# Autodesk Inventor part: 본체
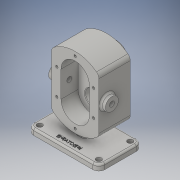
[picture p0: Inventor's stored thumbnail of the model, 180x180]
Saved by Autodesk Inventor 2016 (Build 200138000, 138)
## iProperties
Created: 2019-03
Part Number: 본체
Material: 일반
Document SubType Name: Modeling
Designer: Administrator
Density: 1 g/cm^3
Appearance: 기본값
Mass: 440.333 g
Surface Area: 723.664 cm^2
Volume: 440.333 cm^3
Author: Administrator
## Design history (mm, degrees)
sketch "스케치1"
  geometry: L1 (60, 36.5)-(-60, 36.5); L2 (-60, 36.5)-(-60, -36.5); L3 (-60, -36.5)-(60, -36.5); L4 (60, -36.5)-(60, 36.5); L5 (60, 36.5)-(-60, -36.5); L6 (-60, 36.5)-(60, -36.5); 1 further point
  constraints: 12 end point, 2 midpoint, 2 parallel, 1 horizontal, 1 perpendicular
  dimensions: "d0" = 73 distance of L1.end L2.end; "d1" = 120 distance of L2.end L3.end
extrude "돌출1" new body sketch "스케치1" distance "d2" = 10; taper "d3" = 0 deg
node "작업 평면1"
sketch "스케치2"
  geometry: L1 (0, 0)-(0, 78); L2 (-40, 33.279)-(40, 33.279); L3 (40, 33.279)-(40, 122.721); L4 (-40, 122.721)-(-40, 33.279); L5 (-40, 33.279)-(40, 122.721); L6 (40, 33.279)-(-40, 122.721); L7 (-46.037, 78)-(46.038, 78); A1 r 60 centre (0, 78) between (40, 122.721) and (-40, 122.721); A2 r 60 centre (0, 78) between (-40, 33.279) and (40, 33.279); 2 further points
  constraints: 14 end point, 5 midpoint, 4 point on circle, 2 centre point, 2 horizontal, 1 coincident, 1 parallel, 1 perpendicular, 1 vertical
  dimensions: "d5" = 78 distance of L1.start L1.end; "d6" = 80 distance between parallel lines of L3 L4; "d7" = 60 radius of A1; "d8" = 60 radius of A2
extrude "돌출2" join sketch "스케치2" distance "d9" = 53; taper "d10" = 0 deg
sketch "스케치3"
  geometry: L1 (0, 0)-(0, 78); L2 (-54.769, 78)-(54.769, 78); L3 (0, 100)-(0, 56); L4 (-24, 100)-(-24, 56); L5 (24, 56)-(24, 100); A1 r 24 centre (0, 100) between (24, 100) and (-24, 100); A2 r 24 centre (0, 56) between (-24, 56) and (24, 56); 1 further point
  constraints: 12 end point, 4 point on circle, 4 tangent, 2 centre point, 2 midpoint, 1 coincident, 1 horizontal, 1 parallel, 1 point on line, 1 vertical
  dimensions: "d11" = 78 distance of L1.end L1.start; "d12" = 22 distance of L1.end L3.start; "d13" = 24 radius of A1
extrude "돌출3" cut sketch "스케치3" distance "d14" = 29; taper "d15" = 0 deg
sketch "스케치4"
  geometry: L1 (0, 0)-(0, 78); C1 r 12.5 at (0, 100); C2 r 12.5 at (0, 56)
  constraints: 2 centre point, 2 end point, 2 point on line, 1 equal radius, 1 vertical
  dimensions: "d16" = 78 distance of L1.start L1.end; "d17" = 22 distance of L1.end C1.centre; "d18" = 22 distance of L1.end C2.centre; "d19" = 25 diameter of C1
extrude "돌출4" cut sketch "스케치4" distance "d20" = 15; taper "d21" = 0 deg
sketch "스케치5"
  geometry: C1 r 12.5 at (0, 100) reference; C2 r 19 at (0, 100); 1 further point
  constraints: 1 centre point, 1 concentric
  dimensions: "d22" = 38 diameter of C2
extrude "돌출5" join sketch "스케치5" distance "d23" = 17; taper "d24" = 0 deg
fillet "모깎기1" dims "d29" = 10
fillet "모깎기2" dims "d30" = 3
sketch "스케치7"
  geometry: L1 (-50, 36.5)-(-50, 33.5) reference; L2 (-50, 33.5)-(50, 33.5) reference; L3 (50, 36.5)-(50, 33.5) reference; L4 (50, 36.5)-(-50, 36.5) reference; L5 (-6, 36.5)-(6, 36.5); L6 (6, 36.5)-(6, -6.5); L7 (6, -6.5)-(-6, -6.5); L8 (-6, -6.5)-(-6, 36.5); 1 further point
  constraints: 8 end point, 2 parallel, 1 horizontal, 1 perpendicular, 1 point on line
  dimensions: "d31" = 43 distance of L5.end L6.end; "d32" = 6 distance from line of point (0, 0) L6; "d33" = 6 distance from line of point (0, 0) L8
extrude "돌출6" join sketch "스케치7" stored distance "d34" = 7.3; taper "d35" = 0 deg; dims "d8" = 60
fillet "모깎기3" dims "d36" = 3
fillet "모깎기4" dims "d37" = 10
sketch "스케치8"
  geometry: L1 (81, -53.5)-(119, -53.5) reference; L2 (100, -53.5)-(100, -46.2); L3 (100, -46.2)-(114, -46.2); L4 (114, -46.2)-(114, -52.8); L5 (100, -53.5)-(114.404, -53.5); L6 (114, -52.8)-(114.404, -53.5); 1 further point
  constraints: 10 end point, 1 midpoint, 1 perpendicular, 1 vertical
  dimensions: "d38" = 7.3 distance of L2.start L2.end; "d39" = 14 distance of L2.end L3.end; "d42" = 30 deg angle of L6 L4; "d43" = 6.6 distance of L3.end L4.end
revolve "회전2" sketch "스케치8" stored, may be unused: angle "d44" = 90 deg
sketch "스케치9"
  geometry: C1 r 8.5 at (0, 0); C2 r 19 at (0, 0) reference; 1 further point
  constraints: 1 centre point, 1 concentric
  dimensions: "d45" = 17 diameter of C1
extrude "돌출7" cut sketch "스케치9" stored distance "d46" = 7.3; taper "d47" = 0 deg
chamfer "모따기1" distance "d48" = 1; stored, may be unused: second distance "d49" = 2, angle "d50" = 45 deg
chamfer "모따기2" distance "d51" = 1; stored, may be unused: second distance "d52" = 2, angle "d53" = 45 deg
hole "구멍1" diameter "d56" = 9; stored, may be unused: countersink angle "d60" = 90 deg, drill point angle "d62" = 0 deg; dims "d54" = 10, "d55" = 10, "d57" = 6, "d58" = 4, "d59" = 2, "d61" = 10
hole "구멍2" diameter "d65" = 9; stored, may be unused: countersink angle "d69" = 90 deg, drill point angle "d71" = 0 deg; dims "d63" = 10, "d64" = 10, "d66" = 6, "d67" = 4, "d68" = 2, "d70" = 10
hole "구멍3" diameter "d74" = 9; stored, may be unused: countersink angle "d78" = 90 deg, drill point angle "d80" = 0 deg; dims "d72" = 10, "d73" = 10, "d75" = 6, "d76" = 4, "d77" = 2, "d79" = 10
hole "구멍4" diameter "d83" = 9; stored, may be unused: countersink angle "d87" = 90 deg, drill point angle "d89" = 0 deg; dims "d81" = 10, "d82" = 10, "d84" = 6, "d85" = 4, "d86" = 2, "d88" = 10
fillet "모깎기5" dims "d90" = 3
feature "두껍게 하기1" dims "d91" = 2, "d92" = 2
feature "두껍게 하기2" dims "d93" = 1, "d94" = 1
fillet "모깎기6" dims "d95" = 3
sketch "스케치10"
  geometry: L1 (0, 0)-(0, 78); L2 (0, 100)-(0, 56); L3 (-31, 100)-(-31, 56); L4 (31, 56)-(31, 100); L5 (-31, 100)-(31, 100); L6 (-31, 56)-(31, 56); A1 r 31 centre (0, 100) between (31, 100) and (-31, 100); A2 r 31 centre (0, 56) between (-31, 56) and (31, 56); 9 further points
  constraints: 14 end point, 6 coincident, 6 point on circle, 4 tangent, 2 centre point, 2 horizontal, 1 midpoint, 1 parallel, 1 vertical, 1 vertical alignment, 1 other
  dimensions: "d96" = 78 distance of L1.start L1.end; "d97" = 31 radius of A1; "d98" = 44 distance of L2.end point (0, 100)
hole "구멍5" sketch "스케치10" at (0, 131), (0, 25), (-31, 56), (31, 56), (31, 100), (-31, 100) diameter "d99" = 4.134; stored, may be unused: countersink angle "d103" = 90 deg, drill point angle "d105" = 120 deg; dims "d100" = 10, "d101" = 4, "d102" = 2, "d104" = 12
sketch "스케치12"
  geometry: L1 (-50, -36.5)-(50, -36.5) reference; L2 (0, -36.5)-(0, -26.5); 2 further points
  constraints: 2 end point, 1 coincident, 1 midpoint, 1 vertical, 1 other
  dimensions: "d131" = 10 distance of L2.start L2.end
feature "엠보싱1" sketch "스케치12" dims "d132" = 0.5, "d133" = 0
sketch "스케치13"
  geometry: L1 (-53, 18)-(-53, 62) reference; L2 (-53, 40)-(-39, 40); C1 r 11 at (-39, 40); 1 further point
  constraints: 2 end point, 1 centre point, 1 coincident, 1 horizontal, 1 midpoint
  dimensions: "d134" = 14 distance of L2.start L2.end; "d135" = 22 diameter of C1
extrude "돌출8" join sketch "스케치13" distance "d136" = 8; taper "d137" = 0 deg
fillet "모깎기9" dims "d138" = 3
hole "구멍8" diameter "d141" = 8.376; stored, may be unused: countersink angle "d145" = 90 deg, drill point angle "d147" = 118 deg; dims "d139" = 10, "d140" = 10, "d142" = 20, "d143" = 4, "d144" = 2, "d146" = 27.3
hole "구멍9" diameter "d150" = 8.376; stored, may be unused: countersink angle "d154" = 90 deg, drill point angle "d156" = 118 deg; dims "d148" = 10, "d149" = 10, "d151" = 20, "d152" = 4, "d153" = 2, "d155" = 27.3
fillet "모깎기10" dims "d157" = 0.5
node "솔리드1"
mirror "대칭2"
node "투영된 루프1"
other parameters: "d4" = -36.5
